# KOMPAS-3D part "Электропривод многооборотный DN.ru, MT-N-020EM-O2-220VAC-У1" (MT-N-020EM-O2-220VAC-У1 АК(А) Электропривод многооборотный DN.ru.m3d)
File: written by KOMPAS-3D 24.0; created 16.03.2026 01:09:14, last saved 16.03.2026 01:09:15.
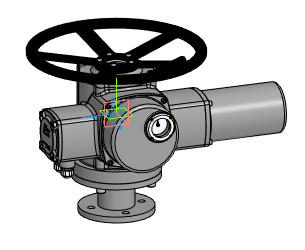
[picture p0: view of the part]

Document properties: Автор: DN.RU; Полное имя файла: D:\PROJECT CAD\DN.RU\...193.(ACTUALE) MT-N-xEM-O2-x-У1 Электропривод многооборотный DN.ru\MT-N-020EM-O2-220VAC-У1 АК(А)\MT-N-020EM-O2-220VAC-У1 АК(А) Электропривод многооборотный DN.ru.m3d

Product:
- Body: Твердое тело1  | qty 1
    Масса: 74.091729
- Part/product: Электропривод многооборотный DN.ru  | designation MT-N-020EM-O2-220VAC-У1
    Масса: 12
    Раздел спецификации: Прочие изделия
    Комментарий: D300-04891
    Примечание: D300-04891
    additional columns: Сталь

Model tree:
1. Твердое тело1  (labels: Твердое тело1)

Expressions: MT-N-020EM-O2-220VAC-У1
